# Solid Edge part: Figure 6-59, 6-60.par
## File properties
Author: CADCIM
Template: Normal.par
Last saved by: CADCIM
Revision: 5
Application: Solid Edge
Accuracy: 0.99
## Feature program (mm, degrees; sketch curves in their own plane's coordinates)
sketch for "unnamed Protrusion 1" plane through (0, 0, 0) normal (0, 0, 1) x-axis (1, 0, 0)
  line (-47.1273, -23.8442) -> (49.3714, -23.8442)
  line (49.3714, -23.8442) -> (49.3714, 37.8701)
  line (49.3714, 37.8701) -> (-47.1273, 37.8701)
  line (-47.1273, 37.8701) -> (-47.1273, -23.8442)
extrude "unnamed Protrusion 1" add finite 12.7 symmetric
sketch for "unnamed Cutout 1" plane through (1.1221, 7.013, 6.35) normal (0, 0, 1) x-axis (1, 0, 0)
  line (-36.3186, 2.9827) -> (-28.5987, 2.9827)
  line (-28.5987, 2.9827) -> (-28.5987, -2.9827)
  line (-28.5987, -2.9827) -> (-36.3186, -2.9827)
  line (-36.3186, -2.9827) -> (-36.3186, 2.9827)
extrude "unnamed Cutout 1" cut through along -normal
pattern "PatternOccurrence_2" of "unnamed Cutout 1" along a curve  XDirCount = 8; YDirCount = 2
pattern "unnamed Pattern 1"
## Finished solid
Body 1: solid body, 38 faces, 108 edges, 72 vertices.
  Faces by surface: plane 38
  Edges by curve: line 108
Bounding box of the edges (mm): 96.499 x 61.714 x 12.700, from (-47.1273, -23.8442, -6.35) to (49.3714, 37.8701, 6.35).
Planar faces by outward normal: +x 3, +y 3, +z 1, -x 3, -y 3, -z 1, oblique 24
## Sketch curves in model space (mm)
arc centre (1.2098, -8.5145, 6.35) radius 40.8417 from (-35.1965, 9.9957, 6.35) through (2.4243, 32.3092, 6.35) to (37.6161, 9.9957, 6.35)
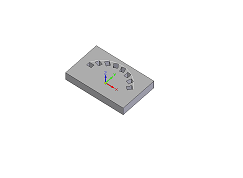
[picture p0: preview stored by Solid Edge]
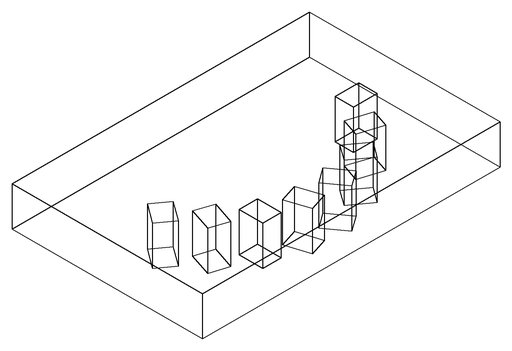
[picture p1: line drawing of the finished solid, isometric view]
